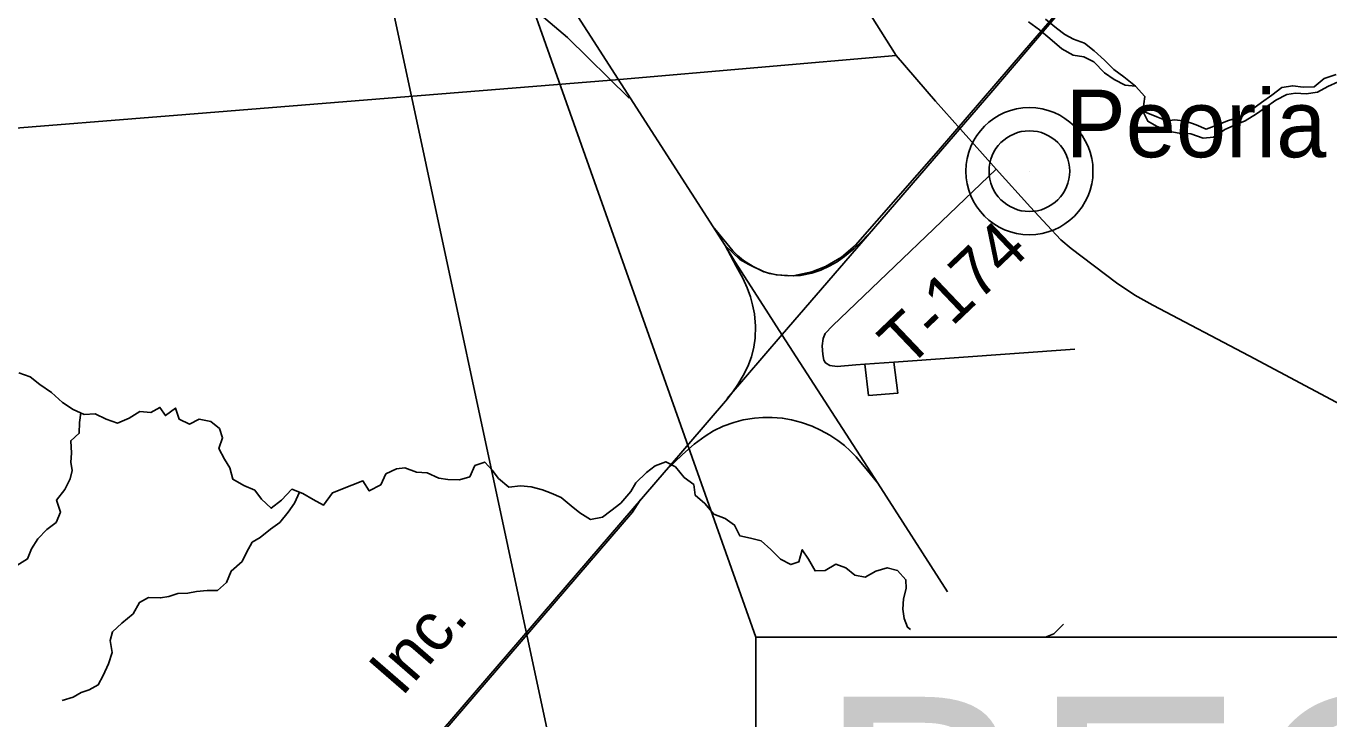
# Model space of a CAD drawing. Extents: x 0 to 34, y 0 to 22.
# Drawn here: x 4.77 to 5.532, y 14.924 to 15.329 of the extents above; entities that cross this region are included whole.
import ezdxf

# ---------------------------------------------------------------- set-up
doc = ezdxf.new("R2010")
doc.units = 0
for name, color, linetype in [('GM_X_County_Road', 7, 'Continuous'), ('GM_X_Minor_River', 7, 'Continuous'), ('GM_X_Rail_Line', 7, 'Continuous'), ('GM_X_Rail_Line_Text', 7, 'Continuous'), ('GM_X_Township_Road', 7, 'Continuous'), ('GM_X_Township_Road_Text', 7, 'Continuous'), ('GM_X_Unincorporated', 7, 'Continuous'), ('GM_X_Unincorporated_Location', 7, 'Continuous'), ('GM_X_Unincorporated_Text', 7, 'Continuous'), ('SH_Text', 7, 'Continuous')]:
    doc.layers.add(name, color=color, linetype=linetype)

msp = doc.modelspace()

# ---------------------------------------------------------------- linework, layer by layer
at = {"layer": 'GM_X_County_Road'}
for points in [[(5.57836, 15.08677), (5.48556, 15.13609), (5.4293, 15.16578), (5.41883, 15.1717), (5.40807, 15.17885), (5.38156, 15.19893), (5.37557, 15.20405), (5.36741, 15.2125), (5.35766, 15.22305), (5.33768, 15.24534), (5.31683, 15.26876), (5.30209, 15.28504), (5.27906, 15.31173), (5.25891, 15.34383), (5.11957, 15.56983), (5.06651, 15.65664), (4.98053, 15.80534), (4.97493, 15.81333), (4.97028, 15.81941), (4.96586, 15.82383), (4.92435, 15.86339), (4.92003, 15.86847), (4.91864, 15.87087), (4.91787, 15.87287)], [(3.73858, 14.6201), (3.92413, 14.73981), (4.02401, 14.80426), (4.34376, 15.01102), (4.352, 15.01643), (4.35746, 15.02065), (4.35939, 15.0236), (4.36105, 15.02788), (4.36153, 15.03334), (4.361, 15.03869), (4.35907, 15.04329), (4.35215, 15.05378), (4.30603, 15.12588), (4.62047, 15.25782), (4.86354, 15.27723), (5.11731, 15.29779), (5.27906, 15.31173)]]:
    msp.add_lwpolyline(points, dxfattribs=at)
at = {"layer": 'GM_X_Minor_River'}
for points in [[(5.35664, 15.33136), (5.36305, 15.32677), (5.36909, 15.32162), (5.37607, 15.3157), (5.38267, 15.31187), (5.38892, 15.31108), (5.39478, 15.30801), (5.40099, 15.30172), (5.40665, 15.29771), (5.41308, 15.29445), (5.41913, 15.29385)], [(5.41913, 15.29385), (5.41234, 15.2992), (5.40649, 15.30359), (5.40103, 15.30912), (5.395, 15.31446), (5.38934, 15.31905), (5.38291, 15.32136), (5.37781, 15.32404), (5.37291, 15.32767), (5.3665, 15.33302)], [(5.53659, 15.30063), (5.52957, 15.29839), (5.52368, 15.29349), (5.51724, 15.29333), (5.51118, 15.29412), (5.50474, 15.29302), (5.49884, 15.2885), (5.49295, 15.28435), (5.48629, 15.27946), (5.47983, 15.27569), (5.47301, 15.27364), (5.46674, 15.27102), (5.46048, 15.26878), (5.45462, 15.27127), (5.44857, 15.27339), (5.44214, 15.27419), (5.4374, 15.27364), (5.43154, 15.27595), (5.42353, 15.2793)], [(5.41913, 15.29385), (5.42459, 15.28775), (5.42353, 15.2793)], [(5.42353, 15.2793), (5.42641, 15.27332), (5.43151, 15.27045), (5.43832, 15.26757), (5.44569, 15.2662), (5.45156, 15.26598), (5.45875, 15.26347), (5.46481, 15.26401), (5.47146, 15.26853), (5.47811, 15.27134), (5.48323, 15.27359), (5.48988, 15.27773), (5.4952, 15.28131), (5.50129, 15.28564), (5.50774, 15.28902), (5.51267, 15.28975), (5.51892, 15.28934), (5.52555, 15.29025), (5.53163, 15.29364), (5.53771, 15.29645)], [(4.93212, 15.05565), (4.9257, 15.05815), (4.9196, 15.05174), (4.91352, 15.04702), (4.90786, 15.05237), (4.90391, 15.0577), (4.89749, 15.06039), (4.89107, 15.06403), (4.8894, 15.07068), (4.8862, 15.07582), (4.88301, 15.08191), (4.88513, 15.08816), (4.88326, 15.09367), (4.87817, 15.09768), (4.87136, 15.09905), (4.86585, 15.09623), (4.85981, 15.09911), (4.85757, 15.10557), (4.85167, 15.10124), (4.84848, 15.106), (4.84316, 15.10299), (4.83672, 15.1036), (4.83045, 15.09965), (4.82362, 15.09684), (4.817, 15.09915), (4.81058, 15.10222), (4.80414, 15.10187), (4.79771, 15.10475), (4.79149, 15.10896), (4.78508, 15.11469), (4.77828, 15.11947), (4.77262, 15.12386), (4.766, 15.12618)], [(4.80215, 15.10276), (4.80146, 15.09714), (4.80124, 15.09088), (4.7963, 15.08655), (4.79683, 15.07933), (4.79642, 15.07402), (4.79716, 15.06909), (4.79599, 15.06416), (4.79274, 15.0581), (4.78798, 15.05187), (4.79022, 15.04483), (4.78772, 15.03878), (4.78221, 15.03463), (4.77707, 15.02916), (4.77325, 15.02329), (4.77095, 15.01742), (4.76468, 15.01366)], [(5.28753, 14.97613), (5.28568, 14.97752), (5.28381, 14.98265), (5.28308, 14.98797), (5.28349, 14.99404), (5.28504, 15.0001), (5.28487, 15.00523), (5.27998, 15.01056), (5.27393, 15.0123), (5.26729, 15.01025), (5.26102, 15.00668), (5.25497, 15.00785), (5.24969, 15.01224), (5.24383, 15.01436), (5.23756, 15.0106), (5.23169, 15.01044), (5.22793, 15.01729), (5.22417, 15.02281), (5.22224, 15.0158), (5.2175, 15.01412), (5.21146, 15.01737), (5.2058, 15.02291), (5.20015, 15.02806), (5.19391, 15.02961), (5.18766, 15.03097), (5.18467, 15.03725), (5.17919, 15.04107), (5.17258, 15.04357), (5.16731, 15.04986), (5.16165, 15.05463), (5.16074, 15.0609), (5.15508, 15.0651), (5.15, 15.0712), (5.14433, 15.07427), (5.13807, 15.07183), (5.13312, 15.06787), (5.12684, 15.06184), (5.12398, 15.05692), (5.11807, 15.05012), (5.11218, 15.04559), (5.10742, 15.04183), (5.10041, 15.04053), (5.09418, 15.04436), (5.08908, 15.04837), (5.08324, 15.05334), (5.07738, 15.05583), (5.07228, 15.05776), (5.06566, 15.0595), (5.05941, 15.0601), (5.05259, 15.05938), (5.04656, 15.06435), (5.04279, 15.0693), (5.03846, 15.07406), (5.03277, 15.07201), (5.02971, 15.06538), (5.02364, 15.06371), (5.01682, 15.06393), (5.01152, 15.06472), (5.00472, 15.06779), (4.99847, 15.0682), (4.99167, 15.07071), (4.98693, 15.07016), (4.98066, 15.06716), (4.9776, 15.06073), (4.97095, 15.05716), (4.9672, 15.06306), (4.96074, 15.06062), (4.94936, 15.05613), (4.94421, 15.04895), (4.93816, 15.05221), (4.93212, 15.05565)], [(4.9301, 15.05644), (4.92717, 15.04999), (4.92354, 15.04469), (4.91859, 15.03865), (4.91308, 15.03488), (4.90718, 15.02998), (4.90243, 15.02716), (4.89918, 15.02111), (4.8965, 15.016), (4.89004, 15.01034), (4.88735, 15.00371), (4.88221, 14.999), (4.87615, 14.99903), (4.8699, 14.9983), (4.86478, 14.99738), (4.85891, 14.99722), (4.8536, 14.99554), (4.84886, 14.99462), (4.84185, 14.99485), (4.83654, 14.99203), (4.8329, 14.98541), (4.82625, 14.97994), (4.82073, 14.97485), (4.81938, 14.96973), (4.82048, 14.9627), (4.81836, 14.95607), (4.8153, 14.94926), (4.81243, 14.94377), (4.80711, 14.94096), (4.80237, 14.93927), (4.79762, 14.93664), (4.79136, 14.93459)], [(5.37697, 14.97932), (5.37145, 14.97366), (5.36651, 14.9716)]]:
    msp.add_lwpolyline(points, dxfattribs=at)
at = {"layer": 'GM_X_Rail_Line'}
for p, q in [((5.21254, 15.14861), (5.26583, 15.2105)), ((5.18029, 15.11122), (5.21254, 15.14861)), ((5.14472, 15.06953), (5.1804, 15.11095))]:
    msp.add_line(p, q, dxfattribs=at)
for points in [[(5.26583, 15.2105), (5.33567, 15.29137), (5.40941, 15.37775), (5.48991, 15.47067), (5.6406, 15.6155), (5.83424, 15.80173), (6.18812, 16.14257), (6.45824, 16.40221), (6.73523, 16.66813), (7.01365, 16.93639), (7.24354, 17.1561), (7.44209, 17.35095), (7.62627, 17.52649), (7.92956, 17.8183), (8.07725, 17.96232), (8.43659, 18.30894), (8.70085, 18.56216), (8.9, 18.75531)], [(2.87249, 15.85698), (2.91145, 15.85791), (2.96133, 15.85164), (2.99463, 15.84452), (3.20808, 15.79503), (3.74918, 15.67048), (3.93017, 15.6314), (4.30003, 15.5466), (4.60627, 15.4754), (4.9134, 15.40633), (4.99239, 15.38104), (5.02639, 15.36542), (5.06261, 15.34269), (5.08696, 15.3222), (5.12288, 15.28684)], [(5.30918, 14.99809), (5.26841, 15.06169), (5.21253, 15.14817), (5.19961, 15.16836), (5.18483, 15.19134), (5.17906, 15.20066), (5.01796, 15.45104), (4.99067, 15.49354), (4.93323, 15.58238), (4.87238, 15.67701), (4.84244, 15.72356), (4.77984, 15.82092), (4.77125, 15.83439), (4.76602, 15.84214)], [(5.17906, 15.20066), (5.18762, 15.19243), (5.19292, 15.18956), (5.20167, 15.18525), (5.20887, 15.18361), (5.2189, 15.18288), (5.22976, 15.18526), (5.2378, 15.18846), (5.24711, 15.19384), (5.25535, 15.20079), (5.30395, 15.25624), (5.35416, 15.31465), (5.43851, 15.4124), (5.48918, 15.47034), (5.50235, 15.48427), (5.52153, 15.50329), (5.54912, 15.53036), (5.57527, 15.55588), (5.60095, 15.58047), (5.63138, 15.60922), (5.6821, 15.65824), (5.77069, 15.74376), (5.82188, 15.79325), (5.83531, 15.80567)], [(5.17289, 15.2107), (5.18006, 15.20176), (5.18355, 15.19747), (5.18628, 15.1949), (5.18986, 15.19188), (5.19545, 15.18839), (5.20151, 15.18554), (5.20512, 15.18439), (5.20945, 15.18359), (5.21605, 15.18288), (5.22324, 15.18317), (5.22975, 15.18448), (5.23505, 15.18633), (5.24005, 15.18851), (5.24455, 15.19108), (5.24893, 15.19419), (5.25443, 15.19881), (5.25902, 15.20314), (5.26583, 15.2105)], [(5.17906, 15.20066), (5.18562, 15.18857), (5.18947, 15.1815), (5.19199, 15.17597), (5.19387, 15.17063), (5.19516, 15.16589), (5.19634, 15.16079), (5.19679, 15.15348), (5.19664, 15.14656), (5.1958, 15.14127), (5.19447, 15.13554), (5.19234, 15.1299), (5.18972, 15.12476), (5.18661, 15.11933), (5.18359, 15.11508), (5.18028, 15.11078)], [(4.96731, 14.86359), (5.14459, 15.06936), (5.15413, 15.0784), (5.16105, 15.08453), (5.16733, 15.08927), (5.17237, 15.09239), (5.17786, 15.09496), (5.18419, 15.09723), (5.18962, 15.09867), (5.19634, 15.09975), (5.20114, 15.10015), (5.20658, 15.1002), (5.21251, 15.09975), (5.21799, 15.09881), (5.22368, 15.09728), (5.22995, 15.09511), (5.23495, 15.09278), (5.24043, 15.08977), (5.24493, 15.0867), (5.24888, 15.08369), (5.2522, 15.08072), (5.25575, 15.07707), (5.26243, 15.06921), (5.26841, 15.06169)], [(4.31088, 14.1), (4.38137, 14.18178), (4.52796, 14.35203), (4.69211, 14.54357), (4.79909, 14.66666), (4.96821, 14.86282), (5.12489, 15.04467), (5.12947, 15.0518)]]:
    msp.add_lwpolyline(points, dxfattribs=at)
at = {"layer": 'GM_X_Township_Road'}
for points in [[(5.33768, 15.24534), (5.24188, 15.1537), (5.2377, 15.14923), (5.23637, 15.14624), (5.23583, 15.14198), (5.23627, 15.13688), (5.23689, 15.13362), (5.23785, 15.13203), (5.2403, 15.1305), (5.24462, 15.12992), (5.25563, 15.13083)], [(5.25563, 15.13083), (5.26087, 15.13126), (5.27783, 15.13248), (5.38373, 15.14007)], [(5.26087, 15.13126), (5.26302, 15.113), (5.28003, 15.11432), (5.27783, 15.13248)]]:
    msp.add_lwpolyline(points, dxfattribs=at)
at = {"layer": 'GM_X_Unincorporated'}
for radius in [0.0372, 0.02358]:
    msp.add_circle((5.35709, 15.24414), radius, dxfattribs=at)
at = {"layer": 'GM_X_Unincorporated_Location'}
msp.add_line((5.35709, 15.24414), (5.35709, 15.24414), dxfattribs=at)
at = {"layer": 'SH_Text'}
for points in [[(5.19712, 14.34788), (4.85905, 15.92505), (5.19712, 14.97163)], [(5.19712, 14.97163), (7.01995, 14.97163), (7.01995, 14.34788), (5.19712, 14.34788)]]:
    msp.add_lwpolyline(points, close=True, dxfattribs=at)

# ---------------------------------------------------------------- texts
at = {"layer": 'GM_X_Rail_Line_Text'}
msp.add_text('Inc.', height=0.028314, rotation=49.06904, dxfattribs=at).set_placement((4.98991, 14.9363))
at = {"layer": 'GM_X_Township_Road_Text'}
msp.add_text('T-174', height=0.028409, rotation=43.61121, dxfattribs=at).set_placement((5.28587, 15.12814))
at = {"layer": 'GM_X_Unincorporated_Text'}
msp.add_text('Peoria', height=0.039489, rotation=0.00001, dxfattribs=at).set_placement((5.37821, 15.25227))
at = {"layer": 'SH_Text'}
msp.add_text('BEGIN PROJECT  ', height=0.14, dxfattribs=at).set_placement((5.23306, 14.79681))

doc.saveas('drawing.dxf')
